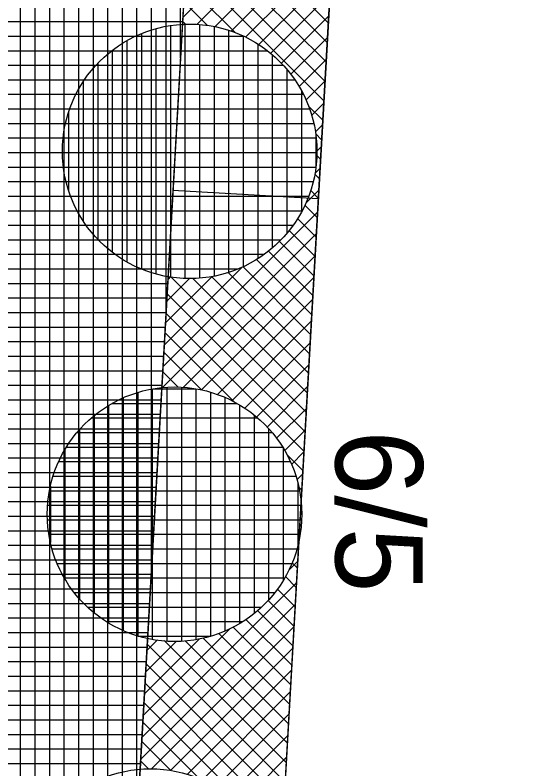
# Model space of a CAD drawing. Extents: x -565346 to -564154, y -1097386 to -1095620.
# Drawn here: x -564294.07 to -564286.86, y -1097238.87 to -1097228.5 of the extents above; entities that cross this region are included whole.
import ezdxf

# ---------------------------------------------------------------- set-up
doc = ezdxf.new("R2010")
doc.units = 0
for name, color, linetype in [('Vrstva 13', 7, 'Continuous'), ('Vrstva 40', 7, 'Continuous'), ('Vrstva 41', 7, 'Continuous'), ('Vrstva 42', 7, 'Continuous'), ('Vrstva 43', 7, 'Continuous'), ('Vrstva 44', 7, 'Continuous')]:
    doc.layers.add(name, color=color, linetype=linetype)

msp = doc.modelspace()

# ---------------------------------------------------------------- linework, layer by layer
at = {"layer": 'Vrstva 13'}
msp.add_line((-564287.03, -1097180.53), (-564291.2, -1097253.99), dxfattribs=at)
at = {"layer": 'Vrstva 41'}
msp.add_line((-564289.904, -1097231.027), (-564291.898, -1097230.914), dxfattribs=at)
msp.add_lwpolyline([(-564297.082, -1097322.329), (-564302.848, -1097333.175), (-564300.817, -1097333.615), (-564295.11, -1097322.88), (-564285.364, -1097151.156), (-564287.358, -1097151.043), (-564289.027, -1097180.417), (-564293.197, -1097253.877), (-564296.237, -1097307.437)], close=True, dxfattribs=at)
at = {"layer": 'Vrstva 42'}
for p, q in [((-564289.635, -1097226.412), (-564291.758, -1097228.535)), ((-564289.652, -1097226.712), (-564291.569, -1097228.629)), ((-564291.509, -1097226.859), (-564289.76, -1097228.608)), ((-564291.67, -1097226.981), (-564289.775, -1097228.876)), ((-564289.669, -1097227.012), (-564291.317, -1097228.659)), ((-564291.685, -1097227.249), (-564289.79, -1097229.144)), ((-564289.686, -1097227.312), (-564291.095, -1097228.721)), ((-564291.701, -1097227.516), (-564289.806, -1097229.411)), ((-564289.703, -1097227.612), (-564290.896, -1097228.804)), ((-564291.716, -1097227.784), (-564289.821, -1097229.679)), ((-564289.72, -1097227.911), (-564290.715, -1097228.906)), ((-564291.731, -1097228.052), (-564291.042, -1097228.741)), ((-564289.737, -1097228.211), (-564290.552, -1097229.026)), ((-564291.746, -1097228.319), (-564291.422, -1097228.643)), ((-564289.754, -1097228.511), (-564290.405, -1097229.162)), ((-564291.761, -1097228.587), (-564291.721, -1097228.627)), ((-564289.771, -1097228.811), (-564290.274, -1097229.313)), ((-564289.788, -1097229.111), (-564290.159, -1097229.482)), ((-564289.805, -1097229.411), (-564290.063, -1097229.668)), ((-564290.031, -1097229.752), (-564289.836, -1097229.947)), ((-564289.822, -1097229.711), (-564289.988, -1097229.876)), ((-564289.84, -1097230.01), (-564289.937, -1097230.108)), ((-564289.933, -1097230.132), (-564289.851, -1097230.214)), ((-564289.857, -1097230.31), (-564289.914, -1097230.368)), ((-564289.917, -1097230.431), (-564289.866, -1097230.482)), ((-564289.874, -1097230.61), (-564289.943, -1097230.68)), ((-564289.944, -1097230.687), (-564289.881, -1097230.75)), ((-564289.891, -1097230.91), (-564290.064, -1097231.084)), ((-564290, -1097230.914), (-564289.897, -1097231.017)), ((-564290.08, -1097231.116), (-564289.912, -1097231.285)), ((-564289.908, -1097231.21), (-564292.031, -1097233.333)), ((-564290.181, -1097231.299), (-564289.927, -1097231.553)), ((-564290.298, -1097231.464), (-564289.942, -1097231.82)), ((-564289.925, -1097231.51), (-564292.038, -1097233.623)), ((-564290.432, -1097231.613), (-564289.957, -1097232.088)), ((-564290.582, -1097231.746), (-564289.973, -1097232.355)), ((-564289.942, -1097231.81), (-564291.753, -1097233.621)), ((-564290.748, -1097231.863), (-564289.988, -1097232.623)), ((-564290.954, -1097231.974), (-564292.014, -1097233.033)), ((-564290.931, -1097231.962), (-564290.003, -1097232.891)), ((-564291.135, -1097232.041), (-564290.018, -1097233.158)), ((-564291.358, -1097232.095), (-564291.997, -1097232.733)), ((-564291.67, -1097232.123), (-564291.98, -1097232.434)), ((-564291.926, -1097232.097), (-564291.963, -1097232.134)), ((-564291.929, -1097232.096), (-564290.064, -1097233.961)), ((-564291.621, -1097232.122), (-564290.049, -1097233.694)), ((-564289.959, -1097232.109), (-564291.503, -1097233.654)), ((-564291.364, -1097232.096), (-564290.033, -1097233.426)), ((-564291.974, -1097232.334), (-564290.079, -1097234.229)), ((-564289.976, -1097232.409), (-564291.285, -1097233.718)), ((-564291.989, -1097232.602), (-564290.094, -1097234.497)), ((-564289.993, -1097232.709), (-564291.087, -1097233.803)), ((-564292.004, -1097232.869), (-564291.053, -1097233.82)), ((-564290.01, -1097233.009), (-564290.908, -1097233.907)), ((-564292.02, -1097233.137), (-564291.502, -1097233.654)), ((-564290.027, -1097233.309), (-564290.746, -1097234.029)), ((-564292.035, -1097233.404), (-564291.823, -1097233.617)), ((-564290.044, -1097233.609), (-564290.601, -1097234.166)), ((-564290.061, -1097233.909), (-564290.471, -1097234.319)), ((-564290.078, -1097234.208), (-564290.358, -1097234.489)), ((-564290.33, -1097234.543), (-564290.109, -1097234.764)), ((-564290.095, -1097234.508), (-564290.265, -1097234.679)), ((-564290.112, -1097234.808), (-564290.192, -1097234.889)), ((-564290.164, -1097234.992), (-564290.124, -1097235.032)), ((-564290.129, -1097235.108), (-564290.143, -1097235.122)), ((-564290.187, -1097235.819), (-564290.17, -1097235.835)), ((-564290.18, -1097236.008), (-564290.303, -1097236.131)), ((-564290.258, -1097236.03), (-564290.185, -1097236.103)), ((-564290.349, -1097236.222), (-564290.2, -1097236.37)), ((-564290.197, -1097236.308), (-564292.32, -1097238.431)), ((-564290.459, -1097236.394), (-564290.216, -1097236.638)), ((-564290.214, -1097236.607), (-564292.337, -1097238.731)), ((-564290.588, -1097236.549), (-564290.231, -1097236.906)), ((-564290.732, -1097236.687), (-564290.246, -1097237.173)), ((-564290.892, -1097236.81), (-564290.261, -1097237.441)), ((-564291.107, -1097236.935), (-564292.303, -1097238.131)), ((-564290.231, -1097236.907), (-564292.189, -1097238.865)), ((-564291.069, -1097236.916), (-564290.276, -1097237.709)), ((-564291.265, -1097237.002), (-564290.292, -1097237.976)), ((-564291.535, -1097237.08), (-564292.286, -1097237.831)), ((-564291.851, -1097237.113), (-564292.269, -1097237.531)), ((-564292.11, -1097237.089), (-564292.252, -1097237.231)), ((-564292.248, -1097237.152), (-564290.352, -1097239.047)), ((-564292.017, -1097237.099), (-564290.337, -1097238.779)), ((-564291.727, -1097237.106), (-564290.322, -1097238.512)), ((-564291.482, -1097237.068), (-564290.307, -1097238.244)), ((-564290.248, -1097237.207), (-564291.929, -1097238.888)), ((-564292.263, -1097237.419), (-564290.368, -1097239.314)), ((-564290.265, -1097237.507), (-564291.698, -1097238.94)), ((-564292.278, -1097237.687), (-564290.383, -1097239.582)), ((-564290.282, -1097237.807), (-564291.491, -1097239.016)), ((-564292.293, -1097237.955), (-564290.398, -1097239.85)), ((-564290.299, -1097238.107), (-564291.306, -1097239.113)), ((-564292.308, -1097238.222), (-564291.53, -1097239.001)), ((-564290.316, -1097238.407), (-564291.138, -1097239.228)), ((-564292.324, -1097238.49), (-564291.924, -1097238.889)), ((-564290.333, -1097238.706), (-564290.987, -1097239.36)), ((-564292.339, -1097238.757), (-564292.231, -1097238.865))]:
    msp.add_line(p, q, dxfattribs=at)
at = {"layer": 'Vrstva 43'}
for p, q in [((-564291.79, -1097229.091), (-564291.79, -1097096.706)), ((-564291.99, -1097232.614), (-564291.99, -1097100.226)), ((-564292.19, -1097236.137), (-564292.19, -1097103.746)), ((-564292.39, -1097239.661), (-564292.39, -1097107.266)), ((-564292.59, -1097243.184), (-564292.59, -1097110.785)), ((-564292.79, -1097246.707), (-564292.79, -1097114.305)), ((-564292.99, -1097250.23), (-564292.99, -1097117.825)), ((-564293.19, -1097253.754), (-564293.19, -1097121.345)), ((-564293.39, -1097257.278), (-564293.39, -1097124.865)), ((-564293.59, -1097260.802), (-564293.59, -1097128.385)), ((-564293.79, -1097264.325), (-564293.79, -1097131.905)), ((-564293.99, -1097267.849), (-564293.99, -1097135.425)), ((-564298.772, -1097228.59), (-564291.762, -1097228.59)), ((-564298.783, -1097228.79), (-564291.773, -1097228.79)), ((-564298.795, -1097228.99), (-564291.784, -1097228.99)), ((-564298.806, -1097229.19), (-564291.796, -1097229.19)), ((-564298.818, -1097229.39), (-564291.807, -1097229.39)), ((-564298.829, -1097229.59), (-564291.818, -1097229.59)), ((-564298.84, -1097229.79), (-564291.83, -1097229.79)), ((-564298.852, -1097229.99), (-564291.841, -1097229.99)), ((-564298.863, -1097230.19), (-564291.852, -1097230.19)), ((-564298.874, -1097230.39), (-564291.864, -1097230.39)), ((-564298.886, -1097230.59), (-564291.875, -1097230.59)), ((-564298.897, -1097230.79), (-564291.886, -1097230.79)), ((-564298.908, -1097230.99), (-564291.898, -1097230.99)), ((-564298.92, -1097231.19), (-564291.909, -1097231.19)), ((-564298.931, -1097231.39), (-564291.921, -1097231.39)), ((-564298.942, -1097231.59), (-564291.932, -1097231.59)), ((-564298.954, -1097231.79), (-564291.943, -1097231.79)), ((-564298.965, -1097231.99), (-564291.955, -1097231.99)), ((-564298.977, -1097232.19), (-564291.966, -1097232.19)), ((-564298.988, -1097232.39), (-564291.977, -1097232.39)), ((-564298.999, -1097232.59), (-564291.989, -1097232.59)), ((-564299.011, -1097232.79), (-564292, -1097232.79)), ((-564299.022, -1097232.99), (-564292.011, -1097232.99)), ((-564299.033, -1097233.19), (-564292.023, -1097233.19)), ((-564299.045, -1097233.39), (-564292.034, -1097233.39)), ((-564299.056, -1097233.59), (-564292.045, -1097233.59)), ((-564299.067, -1097233.79), (-564292.057, -1097233.79)), ((-564299.079, -1097233.99), (-564292.068, -1097233.99)), ((-564299.09, -1097234.19), (-564292.079, -1097234.19)), ((-564299.101, -1097234.39), (-564292.091, -1097234.39)), ((-564299.113, -1097234.59), (-564292.102, -1097234.59)), ((-564299.124, -1097234.79), (-564292.114, -1097234.79)), ((-564299.135, -1097234.99), (-564292.125, -1097234.99)), ((-564299.147, -1097235.19), (-564292.136, -1097235.19)), ((-564299.158, -1097235.39), (-564292.148, -1097235.39)), ((-564299.17, -1097235.59), (-564292.159, -1097235.59)), ((-564299.181, -1097235.79), (-564292.17, -1097235.79)), ((-564299.192, -1097235.99), (-564292.182, -1097235.99)), ((-564299.204, -1097236.19), (-564292.193, -1097236.19)), ((-564299.215, -1097236.39), (-564292.204, -1097236.39)), ((-564299.226, -1097236.59), (-564292.216, -1097236.59)), ((-564299.238, -1097236.79), (-564292.227, -1097236.79)), ((-564299.249, -1097236.99), (-564292.238, -1097236.99)), ((-564299.26, -1097237.19), (-564292.25, -1097237.19)), ((-564299.272, -1097237.39), (-564292.261, -1097237.39)), ((-564299.283, -1097237.59), (-564292.272, -1097237.59)), ((-564299.294, -1097237.79), (-564292.284, -1097237.79)), ((-564299.306, -1097237.99), (-564292.295, -1097237.99)), ((-564299.317, -1097238.19), (-564292.307, -1097238.19)), ((-564299.329, -1097238.39), (-564292.318, -1097238.39)), ((-564299.34, -1097238.59), (-564292.329, -1097238.59)), ((-564299.351, -1097238.79), (-564292.341, -1097238.79))]:
    msp.add_line(p, q, dxfattribs=at)
msp.add_lwpolyline([(-564283.37, -1096906.18), (-564284.87, -1096930.83), (-564282.373, -1096930.972), (-564294.286, -1097140.634), (-564296.782, -1097140.492), (-564297.42, -1097150.37), (-564294.347, -1097150.646), (-564303.226, -1097307.04), (-564304.096, -1097322.37), (-564304.399, -1097332.838), (-564302.848, -1097333.175), (-564297.082, -1097322.329), (-564293.197, -1097253.877), (-564289.027, -1097180.417), (-564287.358, -1097151.043), (-564285.364, -1097151.156), (-564284.798, -1097141.172), (-564286.791, -1097141.059), (-564274.888, -1096931.397), (-564272.899, -1096931.51), (-564271.475, -1096906.55)], dxfattribs=at)
at = {"layer": 'Vrstva 44'}
for p, q in [((-564291.93, -1097228.646), (-564291.93, -1097232.102)), ((-564291.73, -1097228.627), (-564291.73, -1097232.122)), ((-564291.53, -1097228.631), (-564291.53, -1097232.118)), ((-564291.33, -1097228.658), (-564291.33, -1097232.09)), ((-564292.33, -1097228.756), (-564292.33, -1097231.993)), ((-564292.13, -1097228.687), (-564292.13, -1097232.061)), ((-564291.13, -1097228.709), (-564291.13, -1097232.038)), ((-564292.53, -1097228.854), (-564292.53, -1097231.894)), ((-564292.406, -1097228.79), (-564290.927, -1097228.79)), ((-564290.93, -1097228.789), (-564290.93, -1097231.96)), ((-564290.73, -1097228.897), (-564290.73, -1097231.851)), ((-564292.737, -1097228.99), (-564290.598, -1097228.99)), ((-564292.73, -1097228.985), (-564292.73, -1097231.762)), ((-564290.53, -1097229.045), (-564290.53, -1097231.703)), ((-564292.93, -1097229.166), (-564292.93, -1097231.582)), ((-564292.953, -1097229.19), (-564290.38, -1097229.19)), ((-564290.33, -1097229.245), (-564290.33, -1097231.501)), ((-564293.111, -1097229.39), (-564290.219, -1097229.39)), ((-564293.13, -1097229.419), (-564293.13, -1097231.33)), ((-564293.229, -1097229.59), (-564290.104, -1097229.59)), ((-564290.13, -1097229.537), (-564290.13, -1097231.208)), ((-564293.316, -1097229.79), (-564290.018, -1097229.79)), ((-564293.33, -1097229.837), (-564293.33, -1097230.913)), ((-564293.372, -1097229.99), (-564289.959, -1097229.99)), ((-564293.405, -1097230.19), (-564289.927, -1097230.19)), ((-564289.93, -1097230.157), (-564289.93, -1097230.576)), ((-564293.414, -1097230.39), (-564289.918, -1097230.39)), ((-564293.402, -1097230.59), (-564289.932, -1097230.59)), ((-564293.365, -1097230.79), (-564289.968, -1097230.79)), ((-564293.302, -1097230.99), (-564290.029, -1097230.99)), ((-564293.212, -1097231.19), (-564290.12, -1097231.19)), ((-564293.091, -1097231.39), (-564290.243, -1097231.39)), ((-564292.922, -1097231.59), (-564290.41, -1097231.59)), ((-564292.691, -1097231.79), (-564290.64, -1097231.79)), ((-564292.336, -1097231.99), (-564290.999, -1097231.99)), ((-564292.18, -1097233.641), (-564292.18, -1097237.085)), ((-564292.172, -1097233.64), (-564291.585, -1097233.64)), ((-564291.98, -1097233.619), (-564291.98, -1097237.109)), ((-564291.78, -1097233.619), (-564291.78, -1097237.11)), ((-564291.58, -1097233.641), (-564291.58, -1097237.089)), ((-564292.38, -1097233.69), (-564292.38, -1097237.039)), ((-564291.38, -1097233.686), (-564291.38, -1097237.041)), ((-564292.731, -1097233.84), (-564291.017, -1097233.84)), ((-564292.58, -1097233.765), (-564292.58, -1097236.964)), ((-564291.18, -1097233.759), (-564291.18, -1097236.968)), ((-564292.78, -1097233.868), (-564292.78, -1097236.86)), ((-564290.98, -1097233.862), (-564290.98, -1097236.867)), ((-564293.016, -1097234.04), (-564290.733, -1097234.04)), ((-564292.98, -1097234.01), (-564292.98, -1097236.719)), ((-564290.78, -1097233.999), (-564290.78, -1097236.727)), ((-564293.214, -1097234.24), (-564290.533, -1097234.24)), ((-564293.18, -1097234.199), (-564293.18, -1097236.528)), ((-564290.58, -1097234.189), (-564290.58, -1097236.542)), ((-564293.38, -1097234.472), (-564293.38, -1097236.254)), ((-564293.359, -1097234.44), (-564290.391, -1097234.44)), ((-564290.38, -1097234.457), (-564290.38, -1097236.275)), ((-564293.467, -1097234.64), (-564290.283, -1097234.64)), ((-564293.542, -1097234.84), (-564290.205, -1097234.84)), ((-564293.58, -1097234.979), (-564293.58, -1097235.753)), ((-564290.18, -1097234.934), (-564290.18, -1097235.799)), ((-564293.592, -1097235.04), (-564290.157, -1097235.04)), ((-564293.619, -1097235.24), (-564290.131, -1097235.24)), ((-564293.623, -1097235.44), (-564290.128, -1097235.44)), ((-564293.601, -1097235.64), (-564290.147, -1097235.64)), ((-564293.556, -1097235.84), (-564290.192, -1097235.84)), ((-564293.487, -1097236.04), (-564290.262, -1097236.04)), ((-564293.389, -1097236.24), (-564290.361, -1097236.24)), ((-564293.252, -1097236.44), (-564290.496, -1097236.44)), ((-564293.071, -1097236.64), (-564290.678, -1097236.64)), ((-564292.814, -1097236.84), (-564290.937, -1097236.84)), ((-564292.377, -1097237.04), (-564291.377, -1097237.04))]:
    msp.add_line(p, q, dxfattribs=at)
for centre in [(-564291.666, -1097230.374), (-564291.874, -1097235.364), (-564292.206, -1097240.614)]:
    msp.add_circle(centre, 1.75, dxfattribs=at)

# ---------------------------------------------------------------- texts
at = {"layer": 'Vrstva 40'}
msp.add_text('6/5', height=1.2, rotation=270, dxfattribs=at).set_placement((-564289.66, -1097234.21))

doc.saveas('drawing.dxf')
